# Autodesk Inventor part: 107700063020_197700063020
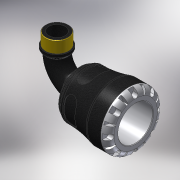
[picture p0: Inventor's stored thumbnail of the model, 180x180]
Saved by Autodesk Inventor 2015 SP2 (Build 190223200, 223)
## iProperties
Created: 2016-12
Part Number: 107700063020_197700063020
Material: PVC-Piping
Description: PLASSON 90° ELBOW WITH MALE INTEGRAL BRASS 63X2" SERIES 1
Document SubType Name: Modeling
Designer: KIM
Mass: 664.223 g
Surface Area: 733.008 cm^2
Volume: 474.445 cm^3
Density: 1.4 g/cm^3
Appearance: Black Cast
Author: KIM
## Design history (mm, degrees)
derived "1077.ipt"
feature "Solid1::1077.ipt"
tag "TaggingFeature1"
body "Solid1"
other parameters: "d1" = 37.8, "d2" = 63, "d3" = 78.75, "d4" = 103, "d8" = 87.55, "d13" = 9.7, "d14" = 9.7, "d15" = 0, "d17" = 360 deg, "d19" = 8 deg, "d20" = 1.26, "d21" = 1.26, "d22" = 8 deg, "d24" = 0, "d26" = 360 deg, "d33" = 10.3, "d43" = 80.34, "d51" = 1.03, "d54" = 22.05, "d55" = 13.86, "d57" = 19.012, "d58" = 0, "d74" = 0, "d82" = 1.26, "d115" = 360 deg, "d207" = 90 deg, "d228" = 18.7425, "d247" = 2.06, "d248" = 5.4, "d268" = 48.1525, "d269" = 5.4, "d270" = 143, "d276" = 59.614, "d277" = 26, "d278" = 65.5754, "d279" = 85, "d280" = 33.8, "d281" = 8.9421, "d283" = 53.6526, "d286" = 0, "d287" = 0, "d288" = 41.7298, "d290" = 13.3437, "d292" = 30 deg, "d294" = 5.9614, "d296" = 30 deg, "d_" = 63, "E_" = 103, "A_" = 143, "A_1" = 85, "l_2" = 26, "R_" = 59.614, "d9" = 12.125, "d11" = 103, "d12" = 78.75, "d289" = 41.7298
